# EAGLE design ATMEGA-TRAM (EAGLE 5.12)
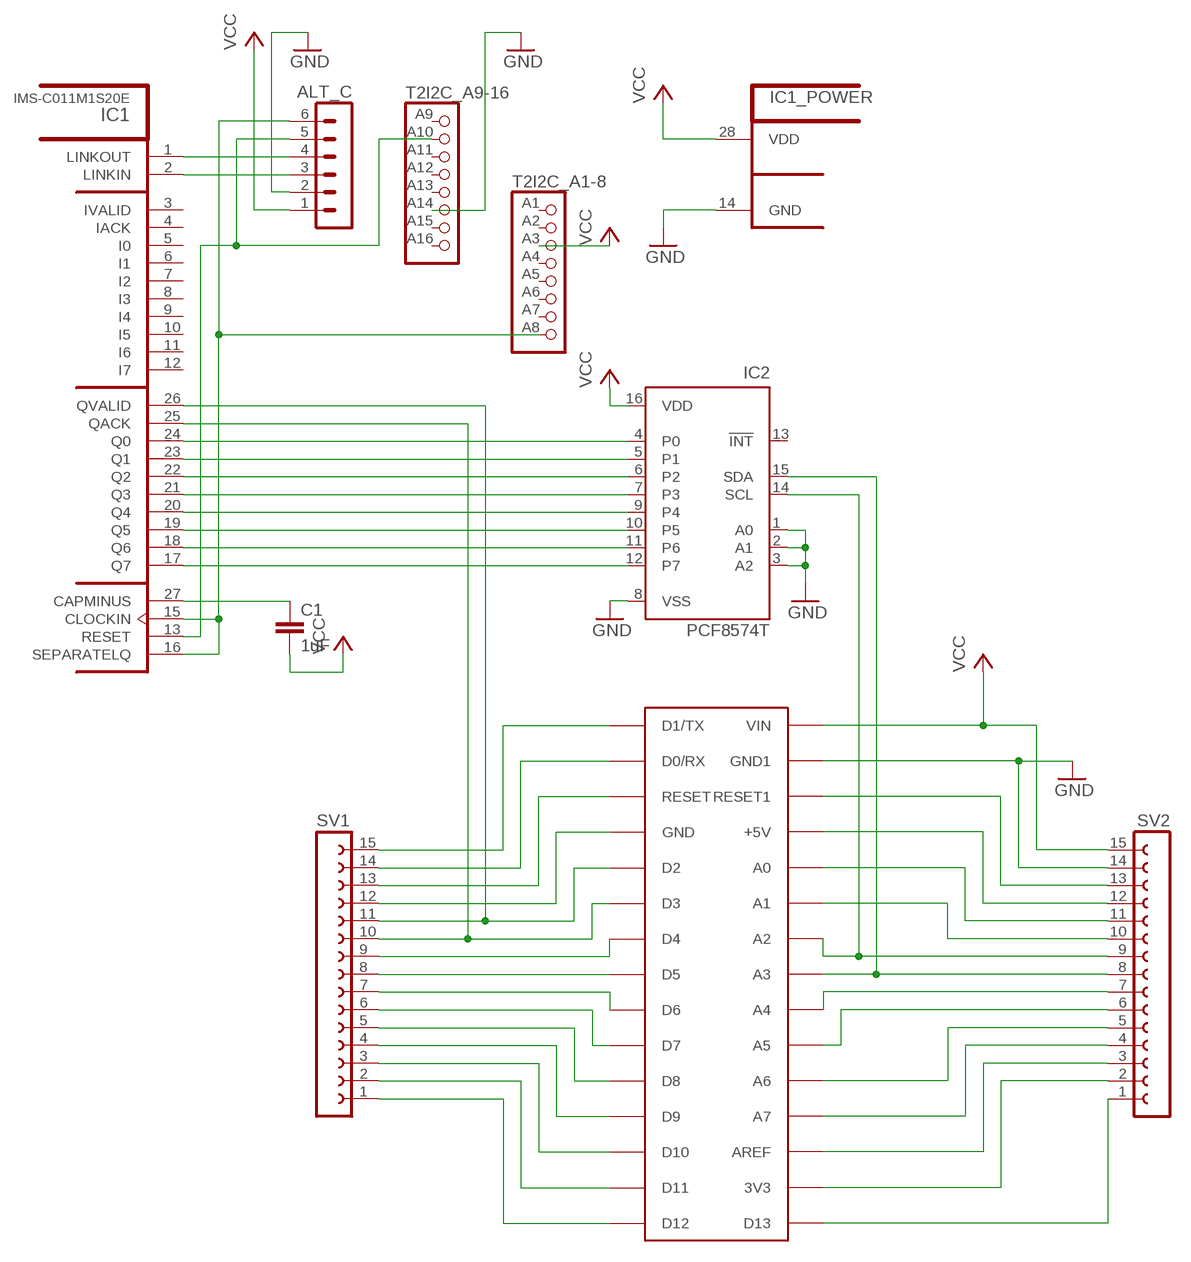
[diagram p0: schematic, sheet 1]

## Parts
ALT_C  MA06-1  [MA06-1]
ARDUINO  ARDUINONANO  [PDIP-32]
C1  1uF  C-EUC0805K  [C0805K]
IC1  IMS-C011M1S20E  [SOJ28-3]
IC2  PCF8574T  [SO16W]
SV1  FE15-1  [FE15]
SV2  FE15-1  [FE15]
T2I2C  TRAM1  [TRAM_SIZE1]

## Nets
GND: ALT_C.2 ARDUINO.GND1 IC1.14(GND) IC2.1(A0) IC2.2(A1) IC2.3(A2) IC2.8(VSS) SV2.14 T2I2C.A14
N$1: ARDUINO.D1/TX SV1.15
N$2: ARDUINO.D0/RX SV1.14
N$3: ARDUINO.RESET SV1.13
N$4: ARDUINO.GND SV1.12
N$5: ARDUINO.D2 IC1.26(QVALID) SV1.11
N$6: ARDUINO.D3 IC1.25(QACK) SV1.10
N$7: ARDUINO.D4 SV1.9
N$8: ARDUINO.D5 SV1.8
N$9: ARDUINO.D6 SV1.7
N$10: ARDUINO.D7 SV1.6
N$11: ARDUINO.D8 SV1.5
N$12: ARDUINO.D9 SV1.4
N$13: ARDUINO.D10 SV1.3
N$14: ARDUINO.D11 SV1.2
N$15: ARDUINO.D12 SV1.1
N$16: ALT_C.4 IC1.1(LINKOUT)
N$17: ALT_C.3 IC1.2(LINKIN)
N$18: ARDUINO.RESET1 SV2.13
N$19: ARDUINO.+5V SV2.12
N$20: ARDUINO.A0 SV2.11
N$21: ARDUINO.A1 SV2.10
N$23: ARDUINO.A2 IC2.14(SCL) SV2.9
N$24: ARDUINO.A4 SV2.7
N$25: ARDUINO.A5 SV2.6
N$26: ARDUINO.A6 SV2.5
N$27: ARDUINO.A7 SV2.4
N$28: ARDUINO.AREF SV2.3
N$29: ARDUINO.3V3 SV2.2
N$30: ARDUINO.D13 SV2.1
N$31: IC1.17(Q7) IC2.12(P7)
N$32: IC1.18(Q6) IC2.11(P6)
N$33: IC1.19(Q5) IC2.10(P5)
N$34: IC1.20(Q4) IC2.9(P4)
N$35: IC1.21(Q3) IC2.7(P3)
N$36: IC1.22(Q2) IC2.6(P2)
N$37: IC1.23(Q1) IC2.5(P1)
N$38: IC1.24(Q0) IC2.4(P0)
N$39: ALT_C.6 IC1.15(CLOCKIN) IC1.16(SEPARATELQ) T2I2C.A8
N$40: ALT_C.5 IC1.13(RESET) T2I2C.A10
N$41: C1.1 IC1.27(CAPMINUS)
N$141: ARDUINO.A3 IC2.15(SDA) SV2.8
VCC: ALT_C.1 ARDUINO.VIN C1.2 IC1.28(VDD) IC2.16(VDD) SV2.15 T2I2C.A3
Unconnected: IC1.3(IVALID) IC1.4(IACK) IC1.5(I0) IC1.6(I1) IC1.7(I2) IC1.8(I3) IC1.9(I4) IC1.10(I5) IC1.11(I6) IC1.12(I7) IC2.13(!INT) T2I2C.A1 T2I2C.A2 T2I2C.A4 T2I2C.A5 T2I2C.A6 T2I2C.A7 T2I2C.A9 T2I2C.A11 T2I2C.A12 T2I2C.A13 T2I2C.A15 T2I2C.A16

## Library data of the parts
ALT_C = con-lstb:MA06-1: PIN HEADER; OC_FARNELL: unknown; OC_NEWARK: unknown
ARDUINO = axels:ARDUINONANO
C1 = rcl:C-EU: CAPACITOR, European symbol
IC1 = Transputers:IMS-C011M1: C011 peripheral mode1 INMOS link adaptor in operation mode 1. Source: The Transputer Databook 1992 INMOS/SGS-Thomson Arto Kyyhkynen, artoky@dlc.fi
IC2 = micro-philips:PCF8574: I2C-Bus Remote 8-bit I/O expander http://www.semiconductors.philips.com/acrobat_download/datasheets/PCF8574_4.pdf; MPN: PCF8574T/3,512; OC_FARNELL: 1201255; OC_NEWARK: 70R6870
SV1 SV2 = axels:FE15-1: FEMALE HEADER; OC_FARNELL: unknown; OC_NEWARK: unknown
T2I2C = axels:TRAM1: TRAM size-1 board INMOS Standard Transputer Boards Simplified version w/o cut-outs Source: The Transputer development and iq systems Databook 1991.

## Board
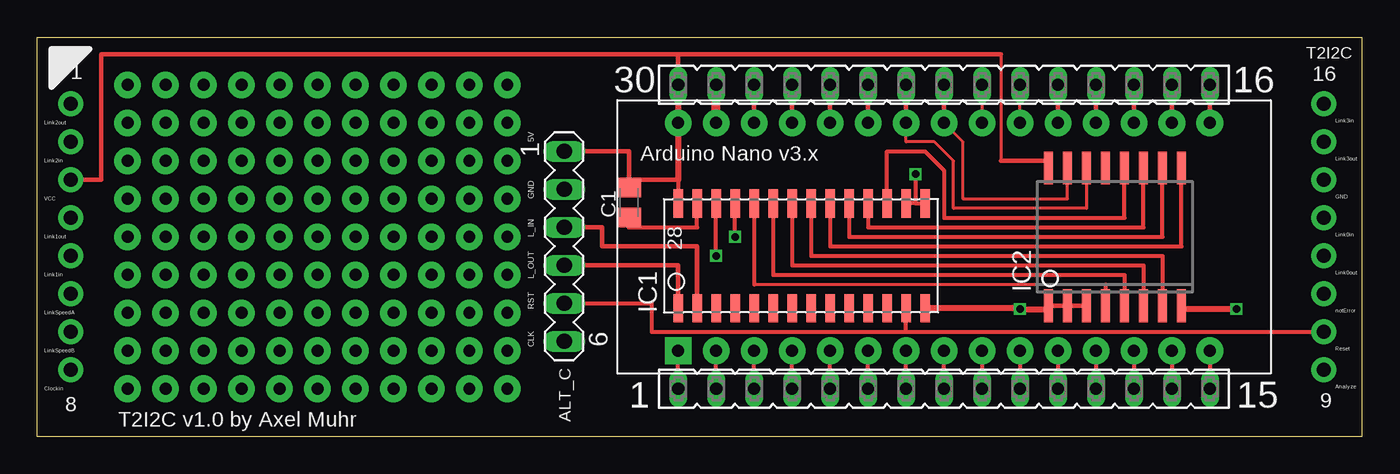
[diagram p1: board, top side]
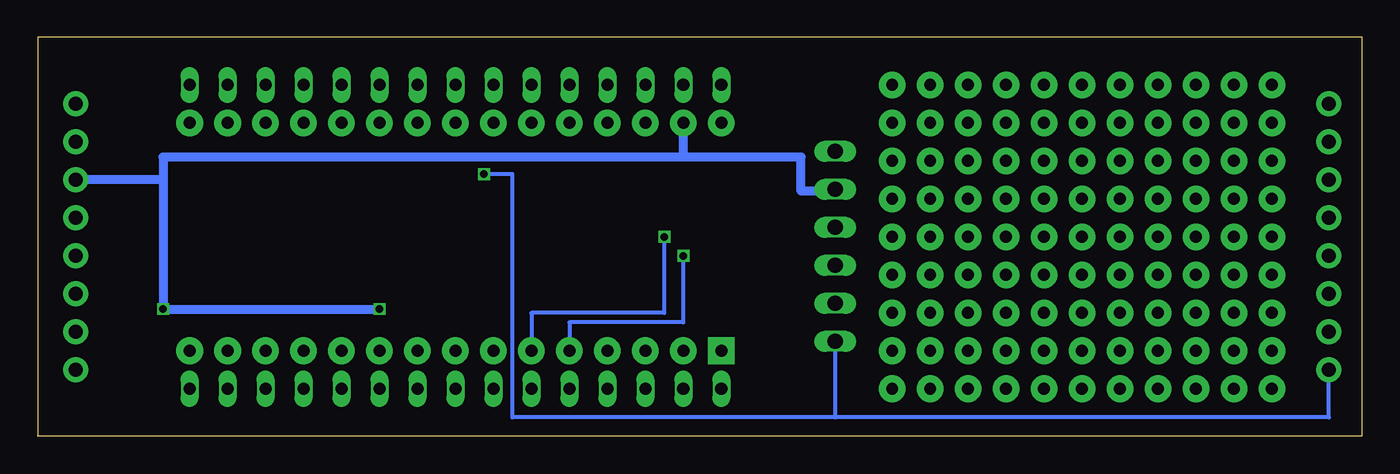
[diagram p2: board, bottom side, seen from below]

Size 88.61 x 26.67 mm. Coordinates in mm from the lower left corner, seen from the top.
Copper layers (1*16): Top 0.035mm / dielectric 1.5mm / Bottom 0.035mm
Design rules "PCB-POOL Standard": minimum track width 0.15mm, minimum drill 0.3mm, track to track 0.15mm, track to pad 0.15mm, pad to pad 0.15mm, via to via 0.15mm, smd to smd 0.15mm, copper to edge 0.3mm, drill to drill 0.2mm, minimum pad ring 0.2mm, minimum via ring 0.15mm, stop-mask expansion 0.075mm, vias tented up to drill 0mil, thermal gap 0.2mm

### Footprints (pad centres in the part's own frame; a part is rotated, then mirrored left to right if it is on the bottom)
MA06-1 = drill 1.016 long: 1 -6.35,0; 2 -3.81,0; 3 -1.27,0; 4 1.27,0; 5 3.81,0; 6 6.35,0
PDIP-32 = drill 0.8 pad 1.778 round: 3V3 15.24,-35.56; +5V 15.24,-10.16; A0 15.24,-12.7; A1 15.24,-15.24; A2 15.24,-17.78; A3 15.24,-20.32; A4 15.24,-22.86; A5 15.24,-25.4; A6 15.24,-27.94; A7 15.24,-30.48; AREF 15.24,-33.02; D0/RX 0,-5.08; D2 0,-12.7; D3 0,-15.24; D4 0,-17.78; D5 0,-20.32; D6 0,-22.86; D7 0,-25.4; D8 0,-27.94; D9 0,-30.48; D10 0,-33.02; D11 0,-35.56; D12 0,-38.1; D13 15.24,-38.1; GND 0,-10.16; GND1 15.24,-5.08; RESET 0,-7.62; RESET1 15.24,-7.62; VIN 15.24,-2.54 | drill 0.8 pad 1.778 square: D1/TX 0,-2.54
C0805K = smd 1.3 x 1.6: 1 -1,0; 2 1,0
SOJ28-3 = smd 0.635 x 1.905: 1 -7.62,-3.505; 2 -6.35,-3.505; 3 -5.08,-3.505; 4 -3.81,-3.505; 5 -2.54,-3.505; 6 -1.27,-3.505; 7 0,-3.505; 8 1.27,-3.505; 9 2.54,-3.505; 10 3.81,-3.505; 11 5.08,-3.505; 12 6.35,-3.505; 13 7.62,-3.505; 14 8.89,-3.505; 15 8.89,3.505; 16 7.62,3.505; 17 6.35,3.505; 18 5.08,3.505; 19 3.81,3.505; 20 2.54,3.505; 21 1.27,3.505; 22 0,3.505; 23 -1.27,3.505; 24 -2.54,3.505; 25 -3.81,3.505; 26 -5.08,3.505; 27 -6.35,3.505; 28 -7.62,3.505
SO16W = smd 0.6 x 2.2: 1 -4.445,-4.6; 2 -3.175,-4.6; 3 -1.905,-4.6; 4 -0.635,-4.6; 5 0.635,-4.6; 6 1.905,-4.6; 7 3.175,-4.6; 8 4.445,-4.6; 9 4.445,4.6; 10 3.175,4.6; 11 1.905,4.6; 12 0.635,4.6; 13 -0.635,4.6; 14 -1.905,4.6; 15 -3.175,4.6; 16 -4.445,4.6
FE15 = drill 0.813 long: 1 -17.78,0; 2 -15.24,0; 3 -12.7,0; 4 -10.16,0; 5 -7.62,0; 6 -5.08,0; 7 -2.54,0; 8 0,0; 9 2.54,0; 10 5.08,0; 11 7.62,0; 12 10.16,0; 13 12.7,0; 14 15.24,0; 15 17.78,0
TRAM_SIZE1 = drill 0.94 pad 1.676 round: A1 0,0; A2 0,-2.54; A3 0,-5.08; A4 0,-7.62; A5 0,-10.16; A6 0,-12.7; A7 0,-15.24; A8 0,-17.78; A9 83.82,-17.78; A10 83.82,-15.24; A11 83.82,-12.7; A12 83.82,-10.16; A13 83.82,-7.62; A14 83.82,-5.08; A15 83.82,-2.54; A16 83.82,0

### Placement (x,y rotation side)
ALT_C  35.24,12.7 270 top
ARDUINO  40.32,5.71 90 top
C1  39.56,15.62 90 top
IC1  50.48,12.06 0 top
IC2  72.07,13.34 0 top
SV1  60.64,3.17 180 top
SV2  60.64,23.49 180 top
T2I2C  2.22,22.23 0 top

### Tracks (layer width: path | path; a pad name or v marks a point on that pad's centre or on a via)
GND  (via drill 0.5)
  Top 0.305: IC2.3 IC2.2 IC2.1 67.63,8.51 | 76.64,8.51 76.64,8.73 IC2.8 | v65.72,8.51 65.72,8.56
  Top 0.406: v80.2,8.51 76.64,8.51 | v65.72,8.51 67.63,8.51 | 65.72,8.56 IC1.14
  Top 0.61: ARDUINO.GND1 SV2.14
  Bottom 0.61: 80.2,17.14 T2I2C.A14 | 80.2,17.14 v80.2,8.51 v65.72,8.51 | ALT_C.2 35.24,16.38 37.53,16.38 37.53,18.67 45.4,18.67 | 45.4,18.67 ARDUINO.GND1 | 45.4,18.67 80.2,18.67 80.2,17.14
N$1
  Top 0.254: SV1.15 ARDUINO.D1/TX
N$2
  Top 0.254: SV1.14 ARDUINO.D0/RX
N$3
  Top 0.254: SV1.13 ARDUINO.RESET
N$4
  Top 0.254: SV1.12 ARDUINO.GND
N$5  (via drill 0.5)
  Top 0.254: v45.4,12.06 IC1.26 | SV1.11 ARDUINO.D2
  Bottom 0.254: v45.4,12.06 45.4,7.62 53.02,7.62 ARDUINO.D2
N$6  (via drill 0.5)
  Top 0.254: v46.67,13.34 IC1.25 | SV1.10 ARDUINO.D3
  Bottom 0.254: v46.67,13.34 46.67,8.26 55.56,8.26 ARDUINO.D3
N$7
  Top 0.254: SV1.9 ARDUINO.D4
N$8
  Top 0.254: SV1.8 ARDUINO.D5
N$9
  Top 0.254: ARDUINO.D6 SV1.7
N$10
  Top 0.254: ARDUINO.D7 SV1.6
N$11
  Top 0.254: ARDUINO.D8 SV1.5
N$12
  Top 0.254: ARDUINO.D9 SV1.4
N$13
  Top 0.254: ARDUINO.D10 SV1.3
N$14
  Top 0.254: ARDUINO.D11 SV1.2
N$15
  Top 0.254: ARDUINO.D12 SV1.1
N$16
  Top 0.254: IC1.1 42.86,8.89
  Top 0.305: IC1.1 42.86,11.43 ALT_C.4
N$17
  Top 0.254: IC1.2 44.13,11.43
  Top 0.305: IC1.2 44.13,12.7 37.78,12.7 37.78,13.97 ALT_C.3
N$18
  Top 0.305: SV2.13 ARDUINO.RESET1
N$19
  Top 0.305: SV2.12 ARDUINO.+5V
N$20
  Top 0.305: SV2.11 ARDUINO.A0
N$21
  Top 0.305: SV2.10 ARDUINO.A1
N$23
  Top 0.203: IC2.14 70.17,15.24 61.28,15.24 61.28,18.41 60.01,19.68 58.1,19.68 ARDUINO.A2
  Top 0.305: ARDUINO.A2 SV2.9
N$24
  Top 0.203: SV2.7 ARDUINO.A4
N$25
  Top 0.203: ARDUINO.A5 SV2.6
N$26
  Top 0.305: SV2.5 ARDUINO.A6
N$27
  Top 0.305: SV2.4 ARDUINO.A7
N$28
  Top 0.305: SV2.3 ARDUINO.AREF
N$29
  Top 0.305: SV2.2 ARDUINO.3V3
N$30
  Top 0.305: SV2.1 ARDUINO.D13
N$31
  Top 0.254: IC1.17 56.83,19.05 59.37,19.05 60.64,17.78 60.64,14.6 72.71,14.6 IC2.12
N$32
  Top 0.254: IC1.18 55.56,13.97 73.98,13.97 IC2.11
N$33
  Top 0.254: IC1.19 54.29,13.34 75.25,13.34 IC2.10
N$34
  Top 0.254: IC1.20 53.02,12.7 76.52,12.7 IC2.9
N$35
  Top 0.254: IC1.21 51.75,12.06 75.25,12.06 IC2.7
N$36
  Top 0.254: IC1.22 50.48,11.43 73.98,11.43 IC2.6
N$37
  Top 0.254: IC1.23 49.21,10.8 72.71,10.8 IC2.5
N$38
  Top 0.203: 47.94,10.16 71.44,10.16
  Top 0.254: 47.94,15.88 47.94,10.16 | 71.44,10.16 IC2.4
  Top 0.406: IC1.24 47.94,15.88
N$39  (via drill 0.5)
  Top 0.254: v58.74,17.53 58.74,15.57 | 58.74,15.57 IC1.16 | 58.74,15.57 IC1.15
  Bottom 0.254: T2I2C.A8 2.22,1.27 35.24,1.27 | 35.24,1.27 56.83,1.27 56.83,17.53 v58.74,17.53 | 35.24,1.27 ALT_C.6
N$40
  Top 0.254: 58.1,6.98 T2I2C.A10 | 58.1,6.98 IC1.13 | ALT_C.5 41.08,8.89 41.08,6.98 58.1,6.98
N$41
  Top 0.254: C1.1 39.56,13.97 44.13,13.97 IC1.27
N$42  (via drill 0.8 pad 1.78)
  other vias: 31.43,23.49
N$43  (via drill 0.8 pad 1.78)
  other vias: 28.89,23.49
N$44  (via drill 0.8 pad 1.78)
  other vias: 26.35,23.49
N$45  (via drill 0.8 pad 1.78)
  other vias: 23.81,23.49
N$46  (via drill 0.8 pad 1.78)
  other vias: 21.27,23.49
N$47  (via drill 0.8 pad 1.78)
  other vias: 18.73,23.49
N$48  (via drill 0.8 pad 1.78)
  other vias: 16.19,23.49
N$49  (via drill 0.8 pad 1.78)
  other vias: 13.65,23.49
N$50  (via drill 0.8 pad 1.78)
  other vias: 11.11,23.49
N$51  (via drill 0.8 pad 1.78)
  other vias: 8.57,23.49
N$52  (via drill 0.8 pad 1.78)
  other vias: 6.03,23.49
N$53  (via drill 0.8 pad 1.78)
  other vias: 31.43,20.96
N$54  (via drill 0.8 pad 1.78)
  other vias: 28.89,20.96
N$55  (via drill 0.8 pad 1.78)
  other vias: 26.35,20.96
N$56  (via drill 0.8 pad 1.78)
  other vias: 23.81,20.96
N$57  (via drill 0.8 pad 1.78)
  other vias: 21.27,20.96
N$58  (via drill 0.8 pad 1.78)
  other vias: 18.73,20.96
N$59  (via drill 0.8 pad 1.78)
  other vias: 16.19,20.96
N$60  (via drill 0.8 pad 1.78)
  other vias: 13.65,20.96
N$61  (via drill 0.8 pad 1.78)
  other vias: 11.11,20.96
N$62  (via drill 0.8 pad 1.78)
  other vias: 8.57,20.96
N$63  (via drill 0.8 pad 1.78)
  other vias: 6.03,20.96
N$64  (via drill 0.8 pad 1.78)
  other vias: 31.43,18.41
N$65  (via drill 0.8 pad 1.78)
  other vias: 28.89,18.41
N$66  (via drill 0.8 pad 1.78)
  other vias: 26.35,18.41
N$67  (via drill 0.8 pad 1.78)
  other vias: 23.81,18.41
N$68  (via drill 0.8 pad 1.78)
  other vias: 21.27,18.41
N$69  (via drill 0.8 pad 1.78)
  other vias: 18.73,18.41
N$70  (via drill 0.8 pad 1.78)
  other vias: 16.19,18.41
N$71  (via drill 0.8 pad 1.78)
  other vias: 13.65,18.41
N$72  (via drill 0.8 pad 1.78)
  other vias: 11.11,18.41
N$73  (via drill 0.8 pad 1.78)
  other vias: 8.57,18.41
N$74  (via drill 0.8 pad 1.78)
  other vias: 6.03,18.41
N$75  (via drill 0.8 pad 1.78)
  other vias: 31.43,15.88
N$76  (via drill 0.8 pad 1.78)
  other vias: 28.89,15.88
N$77  (via drill 0.8 pad 1.78)
  other vias: 26.35,15.88
N$78  (via drill 0.8 pad 1.78)
  other vias: 23.81,15.88
N$79  (via drill 0.8 pad 1.78)
  other vias: 21.27,15.88
N$80  (via drill 0.8 pad 1.78)
  other vias: 18.73,15.88
N$81  (via drill 0.8 pad 1.78)
  other vias: 16.19,15.88
N$82  (via drill 0.8 pad 1.78)
  other vias: 13.65,15.88
N$83  (via drill 0.8 pad 1.78)
  other vias: 11.11,15.88
N$84  (via drill 0.8 pad 1.78)
  other vias: 8.57,15.88
N$85  (via drill 0.8 pad 1.78)
  other vias: 6.03,15.88
N$86  (via drill 0.8 pad 1.78)
  other vias: 31.43,13.34
N$87  (via drill 0.8 pad 1.78)
  other vias: 28.89,13.34
N$88  (via drill 0.8 pad 1.78)
  other vias: 26.35,13.34
N$89  (via drill 0.8 pad 1.78)
  other vias: 23.81,13.34
N$90  (via drill 0.8 pad 1.78)
  other vias: 21.27,13.34
N$91  (via drill 0.8 pad 1.78)
  other vias: 18.73,13.34
N$92  (via drill 0.8 pad 1.78)
  other vias: 16.19,13.34
N$93  (via drill 0.8 pad 1.78)
  other vias: 13.65,13.34
N$94  (via drill 0.8 pad 1.78)
  other vias: 11.11,13.34
N$95  (via drill 0.8 pad 1.78)
  other vias: 8.57,13.34
N$96  (via drill 0.8 pad 1.78)
  other vias: 6.03,13.34
N$97  (via drill 0.8 pad 1.78)
  other vias: 31.43,10.8
N$98  (via drill 0.8 pad 1.78)
  other vias: 28.89,10.8
N$99  (via drill 0.8 pad 1.78)
  other vias: 26.35,10.8
N$100  (via drill 0.8 pad 1.78)
  other vias: 23.81,10.8
N$101  (via drill 0.8 pad 1.78)
  other vias: 21.27,10.8
N$102  (via drill 0.8 pad 1.78)
  other vias: 18.73,10.8
N$103  (via drill 0.8 pad 1.78)
  other vias: 16.19,10.8
N$104  (via drill 0.8 pad 1.78)
  other vias: 13.65,10.8
N$105  (via drill 0.8 pad 1.78)
  other vias: 11.11,10.8
N$106  (via drill 0.8 pad 1.78)
  other vias: 8.57,10.8
N$107  (via drill 0.8 pad 1.78)
  other vias: 6.03,10.8
N$108  (via drill 0.8 pad 1.78)
  other vias: 31.43,8.26
N$109  (via drill 0.8 pad 1.78)
  other vias: 28.89,8.26
N$110  (via drill 0.8 pad 1.78)
  other vias: 26.35,8.26
N$111  (via drill 0.8 pad 1.78)
  other vias: 23.81,8.26
N$112  (via drill 0.8 pad 1.78)
  other vias: 21.27,8.26
N$113  (via drill 0.8 pad 1.78)
  other vias: 18.73,8.26
N$114  (via drill 0.8 pad 1.78)
  other vias: 16.19,8.26
N$115  (via drill 0.8 pad 1.78)
  other vias: 13.65,8.26
N$116  (via drill 0.8 pad 1.78)
  other vias: 11.11,8.26
N$117  (via drill 0.8 pad 1.78)
  other vias: 8.57,8.26
N$118  (via drill 0.8 pad 1.78)
  other vias: 6.03,8.26
N$119  (via drill 0.8 pad 1.78)
  other vias: 31.43,5.71
N$120  (via drill 0.8 pad 1.78)
  other vias: 28.89,5.71
N$121  (via drill 0.8 pad 1.78)
  other vias: 26.35,5.71
N$122  (via drill 0.8 pad 1.78)
  other vias: 23.81,5.71
N$123  (via drill 0.8 pad 1.78)
  other vias: 21.27,5.71
N$124  (via drill 0.8 pad 1.78)
  other vias: 18.73,5.71
N$125  (via drill 0.8 pad 1.78)
  other vias: 16.19,5.71
N$126  (via drill 0.8 pad 1.78)
  other vias: 13.65,5.71
N$127  (via drill 0.8 pad 1.78)
  other vias: 11.11,5.71
N$128  (via drill 0.8 pad 1.78)
  other vias: 8.57,5.71
N$129  (via drill 0.8 pad 1.78)
  other vias: 6.03,5.71
N$130  (via drill 0.8 pad 1.78)
  other vias: 31.43,3.17
N$131  (via drill 0.8 pad 1.78)
  other vias: 28.89,3.17
N$132  (via drill 0.8 pad 1.78)
  other vias: 26.35,3.17
N$133  (via drill 0.8 pad 1.78)
  other vias: 23.81,3.17
N$134  (via drill 0.8 pad 1.78)
  other vias: 21.27,3.17
N$135  (via drill 0.8 pad 1.78)
  other vias: 18.73,3.17
N$136  (via drill 0.8 pad 1.78)
  other vias: 16.19,3.17
N$137  (via drill 0.8 pad 1.78)
  other vias: 13.65,3.17
N$138  (via drill 0.8 pad 1.78)
  other vias: 11.11,3.17
N$139  (via drill 0.8 pad 1.78)
  other vias: 8.57,3.17
N$140  (via drill 0.8 pad 1.78)
  other vias: 6.03,3.17
N$141
  Top 0.203: IC2.15 68.9,15.88 61.91,15.88 61.91,19.68 ARDUINO.A3
  Top 0.305: ARDUINO.A3 SV2.8
VCC
  Top 0.203: 64.45,25.53 64.45,18.41
  Top 0.254: 39.56,17.14 C1.2 | 42.86,17.14 IC1.28 | SV2.15 ARDUINO.VIN
  Top 0.305: 42.86,17.14 39.56,17.14 39.56,19.05 ALT_C.1 | T2I2C.A3 4.25,17.14 4.25,25.53 42.86,25.53 | 42.86,25.53 SV2.15 | IC2.16 67.63,18.41 64.45,18.41 | 42.86,25.53 64.45,25.53
  Top 0.406: SV2.15 42.86,17.14

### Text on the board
tNames: 30 | 16 | 5V | Arduino Nano v3.x | GND | L_IN | L_OUT | RST | CLK | 1 | 15 | T2I2C v1.0 by Axel Muhr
